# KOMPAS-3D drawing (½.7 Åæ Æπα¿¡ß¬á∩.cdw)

Views: Вид 1
Referenced files in \\F-server\проектирование\Проекты\РЗА и ПА Тюменские РС\4. Проект\ПОС\Изменение 2\Графическая часть\: Характеристика.jpg
Referenced files in C:\Program Files\ASCON\KOMPAS-3D V10\Sys\: SPDS.lcs, Graphic.lcs
Referenced files in \\F-server\проектирование\Проекты\РЗА и ПА Тюменские РС\4. Проект\ЭП\Туринская\Рабочая документация\: план располодения оборудования на ПС.cdw
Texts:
  Текст на чертеже
  Размерные надписи
  Шероховатость
  Линия-выноска #1
  Линия-выноска #2
  Линия-выноска #3
  Отклонения формы и база
  Заголовок таблицы
  Ячейка таблицы
  Стрелка вида
  Обозначение изменения
  Фигурная скобка
  Номер узла
  Марка координационной оси
  VRCB
  Выносная надпись
  Обозначение узла
  Марка/позиционное обозначение с линией-выноской
  Марка/позиционное обозначение на линии
  Марка/позиционное обозначение без линии-выноски
  Лит-Масса-Масштаб
  Материал-Предприятие
  Title Specification
  Body Specification ( left align )
  Body Specificaton ( centered )
  Без имени
  Normal
  heading 1
  Знак Знак Знак Знак Знак Знак
  Verdana
  Body Text
  MS Sans Serif
  Txt
  Simplex
  TXT
  Обычный
  Термин
  Список определений
  Адрес
  Цитаты
  Форматированный
  Courier New
  Z-конец формы
  Z-начало формы
  Additional DXF text style 0
  Абзац Знак
  Body Text 3
  Title
  ТекстШаг1
  Шрифт 2.5
  Заголовки
  txt
  heading 2
  AGOpus
  footer
  Денис
  RUSTXT
  Обычный (веб)
  ООббыыччнныыйй
  Definition Term
  Definition List
  Address
  Blockquote
  Preformatted
  z-Bottom of Form
  z-Top of Form
  header
  NormalParagraphStyle
  ссылки
  Подпись в квадратике
  табл
  цепи
  Маркировка
  клеммы, контакты
  тексты табл
  Тексты. 3,2
  ЗОНА_привяз
  текст переноса
  ТТееррммиинн
  ССппииссоокк ооппррееддееллеенниийй
  ААддрреесс
  ЦЦииттааттыы
  ФФооррммааттиирроовваанннныыйй
  Z-ккооннеецц ффооррммыы
  Z-ннааччааллоо ффооррммыы
  GOST 2.304 type A
  rustxt
  heading 8
  heading 3
  heading 6
  heading 7
  russ
  heading 4
  heading 5
  heading 9
  HeliosLight
  Pa3
  Pa1
  Три с половиной
  style2
  Table Contents
  Table Heading
  ГОСТ_МНЕ
  ESK - Обозначение
  маркировка
  ISOCP
  ROMANS
  SIMPLEX
  Текст 3,5
  Tahoma
  CNBNDG+TimesNewRoman
  Subtitle
  FR5
  romanc
  eskd1
  Pa15
  Pa18
  Аппараты
  подписи
  Состав чартежа
  ячейка табл.
  Ссылки
  Пояснения
  Клеммник текст
  CM12
  romans
  gif
  Пояснения 2
  текст табл
  ISOCPEUR
  CC С?т?и?л?ь? П?о? ц?е?н?т?р?у?
  Normal (Web)
  ошиновка
  Топосъемка
  лотки
  Номер
  на плане
  Постоянные здания и сооружения
  ОПУ
  Существующее
  КРУН 10 кВ
  Трансформатор 1Т, маслоприемник
  Существующий
  Трансформатор 2Т, маслоприемник
  Временные здания и сооружения
  III
  Вагон-дом для кратковременного отдых рабочих
  Уборная
  Дизельная электростанция
  Контейнеры для ТБО (0,75м 3 ) и жидких хоз.-быт.стоков(1м 3 )
  «Екатерина» 9,0х3,0
  Туалетная кабина "Люкс"
  ОАО ПКТИпромстрой
  АДС 45-Т400 РЯ
  Экспликация зданий и сооружений
  Примечания:
  1. Для нужд строительства (размещение задействованного в строительстве персонала, обеспечение
  электроэнергией) использовать временные мобильные инвентарные здания;
  2. При выполнении всех строительно-монтажных работ на площадке необходимо руководствоваться требованиями
  СНиП 12-03-2001 "Безопасность труда в строительстве. Общие требования", СНиП 12-04-2002 "Безопасность
  труда в строительстве. Строительное производство", а также ПОТ-РМ-016-2001/РД 153-34.0-03.150-00
  "Межотраслевые правила по охране труда (правила безопасности) при эксплуатации электроустановок";
  3. Наружное освещение строительной площадки осуществляется за счет существующего освещения;
  4. Под временные сооружения (поз. II, III и IV) устраивается площадка из дорожных плит ПД 60-20 на щебеночном
  основании толщиной 15см;
  5. На период строительства для электроснабжения временных зданий и сооружений использовать дизельную
  электростанцию. Прокладку  кабеля от дизельной электростанции до вагончиков выполнить в воздушном
  исполнении в гофрированной трубе диаметром 30 мм, на вагончиках кабель закрепить скобами. Щиток временного
  электроснабжения навесить на стенку вагона-дома для отдыха рабочих;
  6. Тонкой линией изображено существующее оборудование, замена которого проектом не предусматривается,
  утолщенной - вновь устанавливаемое оборудование.
  7. На паспорте-стенде строительного объекта  должен быть план пожарной защиты с нанесенными
  строящимися и вспомогательными зданиями и сооружениями, въездами, подъездами, местонахождениями
  водоисточников, средств пожаротушения и связи (согласно ППБ-01-03 п.575);
  8. Условные обозначения см. 16/01-ПОС,л.1.
  н.пр.64.19
  н.пр.67.98
  н.пр.66.93
  н.пр.63.61
  н.пр.63.65
  н.пр.63.18
  н.пр.64.50
  н.пр.64.34
  h.забора 57.97
  н.пр.64.73
  h.забора 57.91
  н.пр.60.52
  н.пр.60.25
  h.забора 57.82
  h.забора 58.00
  н.пр.66.71
  н.пр.59.26
  н.пр.59.52
  н.пр.59.49
  ЗРУ 10кВ
  каб. в землю
  н.пр.63.84
  тр-р
  кабель в землю
  б/пр.
  каб.лоток
  ВЛ 110кВ
  ВЛ 10кВ
  емк.для маслослива
  КМУ ИНМАН ИМ-150
  АГП-22
  Характеристика.jpg
  K5LT_BASIC_RGB_0_0_255_THICK_0.6
  CONTI_RGB_168_0_168_THICK_0.13
  CONTI_RGB_168_80_0_THICK_0.13
  CONTI_RGB_0_0_0_THICK_0.13
  CONTI_RGB_0_0_0_THICK_0.3
  POLYLINE_STYLE_0.18_RGB_0_0_0
  K5LT_AXLED_RGB_255_128_0_SC_1_THICK_0.18
  Стили документа
  Бортовой автомобиль КамАЗ 43114-027-02
  АТ ППР#010#0104
  АГП
  Автогидроподъемник АГП-18-04
  АГП ППР#140#0102
  ГИП
  Н.контр.
  Гл.спец
  Провер.
  Разраб.
  Перезавод ВЛ на ПС Тюмень. Реконструкция устройств
  РЗ и ПА на обратных концах отходящих ВЛ,
  ВОЛС Тюменского ТПО
  Матвеев
  Ромин
  Шашерин
  Королева
  ПС 110/10 кВ Туринская
  Строительный генеральный план
  Общие технические условия на средний ремонт
Dimensions and other numbers on the sheet: 16/01-ПОС; 7; 2,5; 1,8; 2.5; 3,2_; 3.5; 3,2; 2,5 (контакты, клеммы); 3,2 (надписи); 3,2 (Зоны); 5; 2,5_01; 2,5_3; 3,5_01; 3,5_tabl; 5_заголовок; 2,3_; 3,2_зона не привяз; 3,5; 3.2 маркировка; 3,2 элементы; 3,2 линия; 3,2 таблица; 2,5 грязносинь; 2.5 курсив; 2.5_Э5_надписи; 2.5_Э5_ссылки; 2.5_кабель; 3.2; 2.5 надписи; 3 и 5; 5,0_белый_подчёркнутый; 3.2 фиол; 3.2 (текст); 1; 2; 3; 4; 56; 58; 56.34; 56.82; 56.51; 56.04; 56.85; 56.28; 56.56; 58.19; 56.60; 56.03; 56.69; 56.23; 56.39; 56.41; 56.59; 56.48; 56.92; 56.66; 57.00; 56.75; 56.91; 56.49; 56.72; 58.61; 56.77; 56.26; 58.53; 56.45; 56.32; 56.90; 56.47; 56.44; 56.95; 56.02; 59.33; 57.36; 58.00; 56.31; 56.29; 58.49; 58.36; 56.79; 56.30; 56.35; 57.74; 56.63; 56.14; 55.97; 57.73; 58.12; 56.62; 58.03; 57.60; 57.94; 56.01; 57.19; 58.43; 58.33; 57.23; 57.34; 57.76; 56.33; 57.77; 57.72; 57.88; 58.23; 56.76; 56.09; 56.73; 57.81; 57.78; 57.24; 58.46; 56.65; 57.80; 58.47; 57.25; 57.39; 56.78; 56.17; 56.71; 56.64; 56.83; 57.05; 57.21; 57.13; 57.18; 56.11; 673250; 673300; 3пр.; 7пр.; 56.99; 56.96; 05.13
